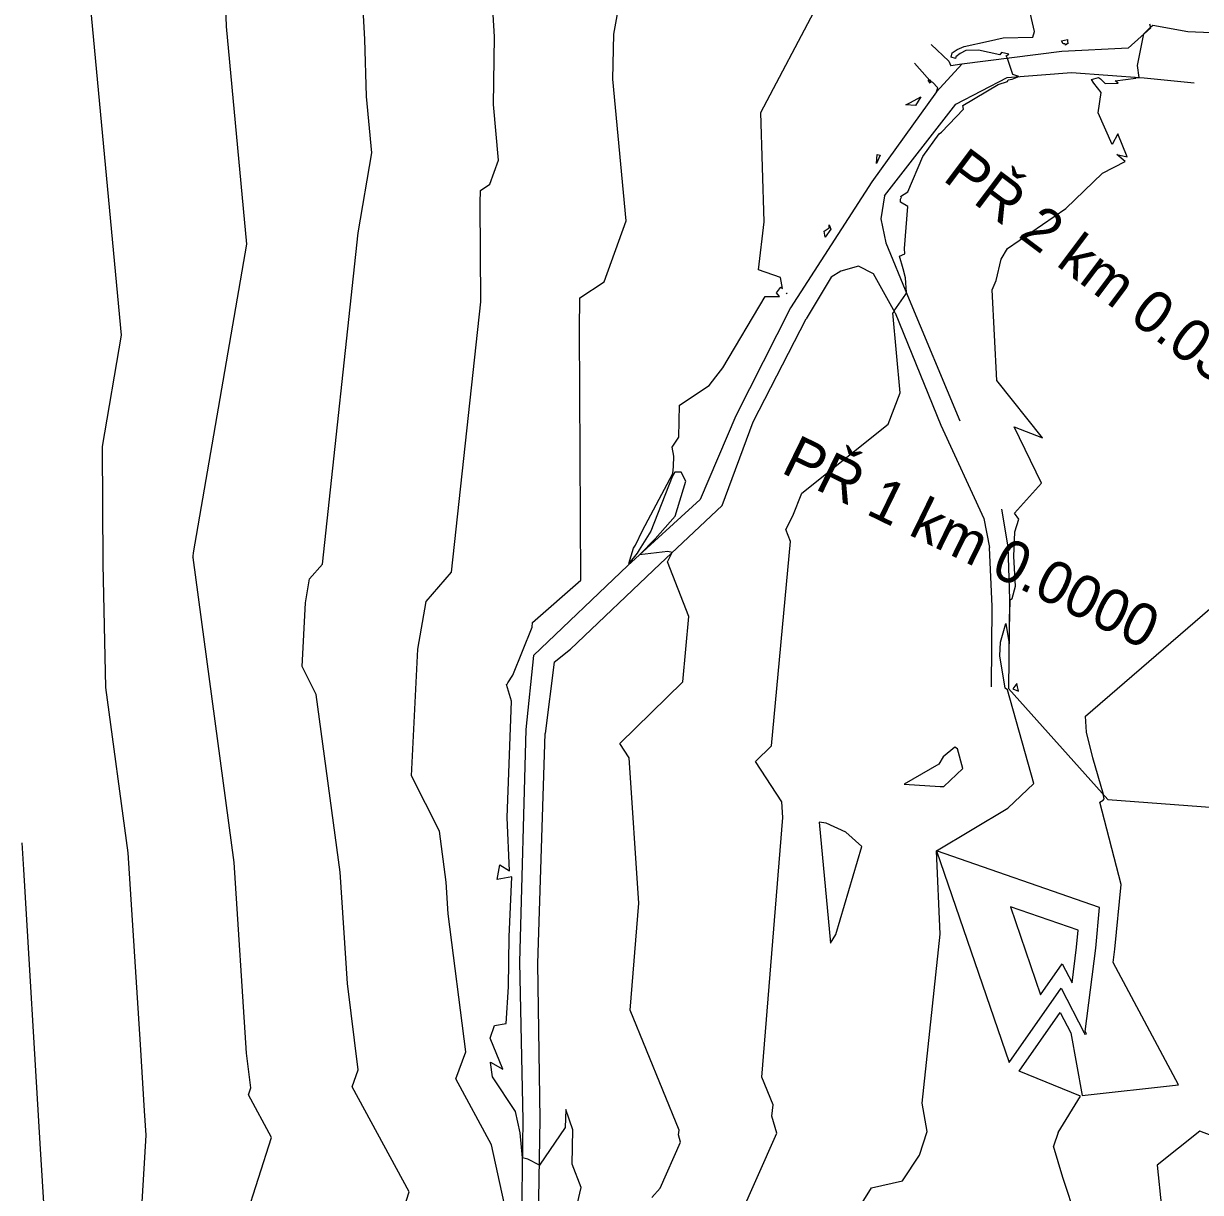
# Model space of a CAD drawing. Extents: x -549394 to -546608, y -1037055 to -1033629.
# Drawn here: x -547750.8 to -547499.1, y -1035351 to -1035100.8 of the extents above; entities that cross this region are included whole.
import ezdxf

# ---------------------------------------------------------------- set-up
doc = ezdxf.new("R2010")
doc.units = 0
for name, color, linetype in [('hlavni_vrst', 7, 'Continuous'), ('hrana_L', 7, 'Continuous'), ('norm_vrst', 7, 'Continuous'), ('x_popis_pricne_rezy_C141', 7, 'Continuous')]:
    doc.layers.add(name, color=color, linetype=linetype)

msp = doc.modelspace()

# ---------------------------------------------------------------- linework, layer by layer
at = {"layer": 'hlavni_vrst'}
for p, q in [((-547650.05, -1035103.66), (-547650.97, -1035088.23)), ((-547650.31, -1035118.13), (-547650.05, -1035103.66)), ((-547649.19, -1035130.07), (-547650.31, -1035118.13)), ((-547651.04, -1035135.21), (-547649.19, -1035130.07)), ((-547653.14, -1035139.23), (-547653.09, -1035136.56)), ((-547653.09, -1035136.56), (-547651.04, -1035135.21)), ((-547653.02, -1035160.36), (-547653.14, -1035139.23)), ((-547659.24, -1035218.22), (-547653.02, -1035160.36)), ((-547664.71, -1035224.5), (-547659.24, -1035218.22)), ((-547666.45, -1035234.7), (-547664.71, -1035224.5)), ((-547523.68, -1035249.07), (-547492.94, -1035222.45)), ((-547667.85, -1035261.83), (-547666.45, -1035234.7)), ((-547523.47, -1035252.45), (-547523.68, -1035249.07)), ((-547522.11, -1035257.98), (-547523.47, -1035252.45)), ((-547519.79, -1035265.79), (-547522.11, -1035257.98)), ((-547661.86, -1035273.67), (-547667.85, -1035261.83)), ((-547520.63, -1035267.42), (-547519.9, -1035266.99)), ((-547516.04, -1035285.05), (-547520.63, -1035267.42)), ((-547519.64, -1035266.74), (-547519.91, -1035265.75)), ((-547519.91, -1035265.75), (-547519.79, -1035265.79)), ((-547519.9, -1035266.99), (-547519.64, -1035266.74)), ((-547660.4, -1035284.55), (-547661.86, -1035273.67)), ((-547659.96, -1035291.34), (-547660.4, -1035284.55)), ((-547517.38, -1035298.89), (-547516.04, -1035285.05)), ((-547516.04, -1035285.05), (-547516.04, -1035285.05)), ((-547516.04, -1035285.05), (-547516.04, -1035285.05)), ((-547516.04, -1035285.05), (-547516.04, -1035285.05)), ((-547516.04, -1035285.05), (-547516.04, -1035285.05)), ((-547656.22, -1035320.85), (-547659.96, -1035291.34)), ((-547517.74, -1035301.73), (-547517.38, -1035298.89)), ((-547503.81, -1035327.94), (-547517.74, -1035301.73)), ((-547537.85, -1035324.99), (-547529.08, -1035312.43)), ((-547529.08, -1035312.43), (-547526.84, -1035316.77)), ((-547526.84, -1035316.77), (-547524.38, -1035330.2)), ((-547658.36, -1035326.65), (-547656.22, -1035320.85)), ((-547524.74, -1035330.33), (-547537.85, -1035324.99)), ((-547650.68, -1035340.75), (-547658.36, -1035326.65)), ((-547524.38, -1035330.2), (-547503.81, -1035327.94)), ((-547529.5, -1035338.11), (-547524.74, -1035330.33)), ((-547499.22, -1035337.83), (-547508.31, -1035345.11)), ((-547490.68, -1035341.09), (-547499.22, -1035337.83)), ((-547529.5, -1035338.11), (-547530.5, -1035341.08)), ((-547647.98, -1035353.14), (-547650.68, -1035340.75)), ((-547528.54, -1035347.72), (-547530.5, -1035341.08)), ((-547508.31, -1035345.11), (-547507.41, -1035354.07)), ((-547522.54, -1035365.68), (-547528.54, -1035347.72))]:
    msp.add_line(p, q, dxfattribs=at)
at = {"layer": 'hrana_L'}
for p, q in [((-547509.73, -1035101.72), (-547509.94, -1035101)), ((-547509.73, -1035101.72), (-547514.54, -1035106.1)), ((-547556.67, -1035105.35), (-547552.91, -1035108.87)), ((-547514.54, -1035106.1), (-547528.76, -1035106.82)), ((-547552.91, -1035108.87), (-547552.47, -1035109.91)), ((-547528.76, -1035106.82), (-547550.14, -1035109.56)), ((-547560.26, -1035109.29), (-547557.54, -1035112.36)), ((-547550.14, -1035109.56), (-547555.52, -1035115.44)), ((-547550.14, -1035109.56), (-547552.47, -1035109.91)), ((-547540.44, -1035112.37), (-547526.63, -1035111.28)), ((-547526.63, -1035111.28), (-547511.12, -1035112.47)), ((-547557.54, -1035112.36), (-547556.92, -1035113.1)), ((-547556.92, -1035113.1), (-547556.4, -1035113.41)), ((-547556.4, -1035113.41), (-547555.25, -1035114.57)), ((-547551.39, -1035118.06), (-547540.44, -1035112.37)), ((-547511.12, -1035112.47), (-547500.41, -1035113.54)), ((-547555.52, -1035115.44), (-547569.35, -1035134.71)), ((-547555.52, -1035115.44), (-547555.25, -1035114.57)), ((-547566.63, -1035137.73), (-547551.39, -1035118.06)), ((-547569.35, -1035134.71), (-547586.77, -1035161.66)), ((-547566.63, -1035137.73), (-547567.41, -1035142.61)), ((-547567.41, -1035142.61), (-547566.36, -1035147.78)), ((-547566.36, -1035147.78), (-547561.74, -1035159)), ((-547575.97, -1035153.82), (-547578.03, -1035155.14)), ((-547572.21, -1035152.78), (-547575.97, -1035153.82)), ((-547569.03, -1035154.36), (-547572.21, -1035152.78)), ((-547578.03, -1035155.14), (-547583.42, -1035164.02)), ((-547564.35, -1035162.73), (-547569.03, -1035154.36)), ((-547561.74, -1035159), (-547550.54, -1035185.88)), ((-547586.77, -1035161.66), (-547598.46, -1035184.75)), ((-547594.73, -1035186.07), (-547583.42, -1035164.02)), ((-547564.35, -1035162.73), (-547554.58, -1035186.78)), ((-547598.46, -1035184.75), (-547606.08, -1035202.67)), ((-547601.35, -1035203.97), (-547594.73, -1035186.07)), ((-547554.58, -1035186.78), (-547545.4, -1035206.76)), ((-547606.08, -1035202.67), (-547621.54, -1035216.83)), ((-547614.62, -1035216.42), (-547601.35, -1035203.97)), ((-547545.4, -1035206.76), (-547544.22, -1035212.97)), ((-547541.65, -1035204.75), (-547540.31, -1035212.84)), ((-547543.64, -1035225.54), (-547544.22, -1035212.97)), ((-547540.31, -1035212.84), (-547539.9, -1035223.97)), ((-547621.54, -1035216.83), (-547641.73, -1035236.08)), ((-547633.84, -1035234.67), (-547614.62, -1035216.42)), ((-547539.9, -1035223.97), (-547540.11, -1035243.13)), ((-547543.79, -1035242.77), (-547543.64, -1035225.54)), ((-547637.32, -1035237.51), (-547633.84, -1035234.67)), ((-547641.73, -1035236.08), (-547643.38, -1035251.89)), ((-547637.32, -1035237.51), (-547639.26, -1035252.74)), ((-547540.11, -1035243.13), (-547518.88, -1035266.9)), ((-547643.38, -1035251.89), (-547644.7, -1035301.66)), ((-547640.79, -1035301.94), (-547639.26, -1035252.74)), ((-547518.88, -1035266.9), (-547496.05, -1035268.59)), ((-547644.7, -1035301.66), (-547643.97, -1035335.51)), ((-547640.27, -1035335.27), (-547640.79, -1035301.94)), ((-547643.97, -1035335.51), (-547644.38, -1035361.94)), ((-547640.75, -1035362.22), (-547640.27, -1035335.27))]:
    msp.add_line(p, q, dxfattribs=at)
at = {"layer": 'norm_vrst'}
for p, q in [((-547624.56, -1035103.1), (-547617.56, -1035064.71)), ((-547707.41, -1035101.49), (-547708.32, -1035068.47)), ((-547677.77, -1035104.15), (-547679.55, -1035074.12)), ((-547729.82, -1035167.54), (-547737.39, -1035086.56)), ((-547593.1, -1035119.88), (-547581.07, -1035097.02)), ((-547534.57, -1035102.57), (-547535.61, -1035097.89)), ((-547509.75, -1035101.64), (-547509.24, -1035101.21)), ((-547509.24, -1035101.21), (-547501.78, -1035102.57)), ((-547703.06, -1035148.01), (-547707.41, -1035101.49)), ((-547624.74, -1035112.74), (-547624.56, -1035103.1)), ((-547544.42, -1035104.64), (-547541.25, -1035103.92)), ((-547541.25, -1035103.92), (-547534.92, -1035103.73)), ((-547534.92, -1035103.73), (-547534.57, -1035102.57)), ((-547512.55, -1035109.82), (-547511.17, -1035103.03)), ((-547511.17, -1035103.03), (-547509.75, -1035101.64)), ((-547501.78, -1035102.57), (-547493.31, -1035102.92)), ((-547677.43, -1035116.42), (-547677.77, -1035104.15)), ((-547552.18, -1035107.09), (-547551.08, -1035106.42)), ((-547551.08, -1035106.42), (-547549.61, -1035105.76)), ((-547549.61, -1035105.76), (-547544.42, -1035104.64)), ((-547528.79, -1035104.51), (-547527.52, -1035104.28)), ((-547528.43, -1035105.18), (-547528.79, -1035104.51)), ((-547528, -1035105.18), (-547528.43, -1035105.18)), ((-547527.97, -1035105.44), (-547528, -1035105.18)), ((-547527.34, -1035105.07), (-547527.97, -1035105.44)), ((-547527.52, -1035104.28), (-547527.55, -1035104.73)), ((-547527.55, -1035104.73), (-547527.34, -1035105.07)), ((-547552.39, -1035108.05), (-547552.18, -1035107.09)), ((-547551.47, -1035108.32), (-547552.39, -1035108.05)), ((-547551.4, -1035107.96), (-547551.47, -1035108.32)), ((-547550.47, -1035107.26), (-547551.4, -1035107.96)), ((-547549.23, -1035106.57), (-547550.47, -1035107.26)), ((-547546.54, -1035106.51), (-547549.23, -1035106.57)), ((-547541.97, -1035107.51), (-547546.54, -1035106.51)), ((-547541.62, -1035107.03), (-547541.97, -1035107.51)), ((-547540.08, -1035107.36), (-547541.62, -1035107.03)), ((-547540.65, -1035107.76), (-547540.08, -1035107.36)), ((-547540.35, -1035108.31), (-547540.65, -1035107.76)), ((-547539.18, -1035111.77), (-547540.35, -1035108.31)), ((-547512.17, -1035112.39), (-547512.55, -1035109.82)), ((-547621.88, -1035143.04), (-547624.74, -1035112.74)), ((-547557.29, -1035112.96), (-547557.19, -1035112.78)), ((-547556.91, -1035113.61), (-547557.29, -1035112.96)), ((-547557.19, -1035112.78), (-547556.86, -1035112.88)), ((-547556.76, -1035113.2), (-547556.91, -1035113.61)), ((-547556.86, -1035112.88), (-547556.76, -1035113.2)), ((-547549.9, -1035118.39), (-547542.36, -1035113.9)), ((-547542.36, -1035113.9), (-547540.37, -1035113.22)), ((-547540.37, -1035113.22), (-547540.19, -1035112.88)), ((-547540.19, -1035112.88), (-547539.36, -1035112.71)), ((-547539.36, -1035112.71), (-547537.9, -1035112.17)), ((-547537.9, -1035112.17), (-547539.18, -1035111.77)), ((-547522.36, -1035112.78), (-547520.92, -1035112.39)), ((-547521.86, -1035113.6), (-547522.36, -1035112.78)), ((-547520.33, -1035115.59), (-547521.86, -1035113.6)), ((-547520.92, -1035112.39), (-547520.45, -1035112.67)), ((-547520.45, -1035112.67), (-547519.48, -1035113.67)), ((-547519.48, -1035113.67), (-547516.67, -1035113.57)), ((-547517.3, -1035113.1), (-547512.88, -1035112.5)), ((-547516.67, -1035113.57), (-547517.3, -1035113.1)), ((-547513.13, -1035112.4), (-547512.17, -1035112.39)), ((-547512.88, -1035112.5), (-547513.13, -1035112.4)), ((-547676.31, -1035128.48), (-547677.43, -1035116.42)), ((-547520.94, -1035119.91), (-547520.33, -1035115.59)), ((-547562.08, -1035118.24), (-547561.09, -1035117.72)), ((-547560.06, -1035118.37), (-547562.08, -1035118.24)), ((-547561.09, -1035117.72), (-547558.85, -1035116.54)), ((-547558.85, -1035116.54), (-547560.06, -1035118.37)), ((-547549.77, -1035119.14), (-547549.9, -1035118.39)), ((-547592.42, -1035143.29), (-547593.1, -1035119.88)), ((-547554.44, -1035124.11), (-547549.77, -1035119.14)), ((-547517.94, -1035126.69), (-547520.94, -1035119.91)), ((-547558.45, -1035129.26), (-547554.97, -1035124.44)), ((-547554.97, -1035124.44), (-547554.44, -1035124.11)), ((-547516.76, -1035124.47), (-547517.94, -1035126.69)), ((-547514.77, -1035129.37), (-547516.76, -1035124.47)), ((-547679.25, -1035145.61), (-547676.31, -1035128.48)), ((-547568.37, -1035130.8), (-547568.19, -1035128.87)), ((-547567.58, -1035129.02), (-547568.37, -1035130.8)), ((-547568.19, -1035128.87), (-547567.58, -1035129.02)), ((-547515.15, -1035130.32), (-547516.97, -1035128.88)), ((-547516.97, -1035128.88), (-547514.77, -1035129.37)), ((-547561.65, -1035136.86), (-547558.45, -1035129.26)), ((-547520.05, -1035132.83), (-547515.15, -1035130.32)), ((-547527.89, -1035140.38), (-547520.05, -1035132.83)), ((-547563.23, -1035137.82), (-547561.65, -1035136.86)), ((-547563.02, -1035137.96), (-547563.23, -1035137.82)), ((-547563.23, -1035139.05), (-547563.22, -1035138.41)), ((-547561.64, -1035139.98), (-547563.23, -1035139.05)), ((-547563.22, -1035138.41), (-547563.02, -1035137.96)), ((-547562.37, -1035148.95), (-547561.64, -1035139.98)), ((-547540.33, -1035148.97), (-547527.89, -1035140.38)), ((-547626.58, -1035156.08), (-547621.88, -1035143.04)), ((-547593.6, -1035153.5), (-547592.42, -1035143.29)), ((-547578.47, -1035144.58), (-547578.46, -1035143.93)), ((-547578.46, -1035143.93), (-547578.12, -1035144.81)), ((-547686.87, -1035216.5), (-547679.25, -1035145.61)), ((-547579.54, -1035145.23), (-547578.47, -1035144.58)), ((-547579.31, -1035146.56), (-547579.54, -1035145.23)), ((-547578.12, -1035144.81), (-547579.31, -1035146.56)), ((-547714.43, -1035214.09), (-547703.06, -1035148.01)), ((-547562.32, -1035150.12), (-547562.37, -1035148.95)), ((-547541.7, -1035151.24), (-547540.33, -1035148.97)), ((-547563.44, -1035150.64), (-547562.32, -1035150.12)), ((-547562.68, -1035153.31), (-547563.44, -1035150.64)), ((-547542.76, -1035155.82), (-547541.7, -1035151.24)), ((-547588.91, -1035155.18), (-547593.6, -1035153.5)), ((-547562.19, -1035155.28), (-547562.68, -1035153.31)), ((-547631.79, -1035159.52), (-547626.58, -1035156.08)), ((-547588.5, -1035157.53), (-547588.91, -1035155.18)), ((-547561.92, -1035158.36), (-547562.19, -1035155.28)), ((-547543.6, -1035157.83), (-547542.76, -1035155.82)), ((-547601.22, -1035174.47), (-547592.16, -1035159.27)), ((-547592.16, -1035159.27), (-547589.1, -1035159.23)), ((-547589.75, -1035158.44), (-547588.88, -1035157.29)), ((-547589.1, -1035159.23), (-547589.75, -1035158.44)), ((-547588.88, -1035157.29), (-547588.86, -1035157.27)), ((-547588.86, -1035157.27), (-547588.5, -1035157.53)), ((-547587.69, -1035158.67), (-547587.56, -1035158.52)), ((-547587.52, -1035158.57), (-547587.69, -1035158.67)), ((-547587.56, -1035158.52), (-547587.5, -1035158.56)), ((-547587.5, -1035158.56), (-547587.52, -1035158.57)), ((-547564.6, -1035162.29), (-547562.12, -1035158.76)), ((-547562.12, -1035158.76), (-547561.93, -1035158.53)), ((-547561.93, -1035158.53), (-547561.92, -1035158.36)), ((-547542.66, -1035177.19), (-547543.6, -1035157.83)), ((-547631.92, -1035166.29), (-547631.79, -1035159.52)), ((-547564.89, -1035162.77), (-547564.66, -1035162.56)), ((-547563.32, -1035179.88), (-547564.89, -1035162.77)), ((-547564.66, -1035162.56), (-547564.6, -1035162.29)), ((-547631.61, -1035219.94), (-547631.92, -1035166.29)), ((-547733.91, -1035191.31), (-547729.82, -1035167.54)), ((-547604.18, -1035178.32), (-547602.75, -1035176.44)), ((-547602.75, -1035176.44), (-547601.22, -1035174.47)), ((-547610.48, -1035182.48), (-547604.18, -1035178.32)), ((-547532.84, -1035189.49), (-547542.66, -1035177.19)), ((-547565.84, -1035186.58), (-547563.32, -1035179.88)), ((-547610.62, -1035189.35), (-547610.48, -1035182.48)), ((-547584.35, -1035201.32), (-547565.84, -1035186.58)), ((-547612.07, -1035191.49), (-547610.62, -1035189.35)), ((-547533.05, -1035199.15), (-547538.95, -1035187.12)), ((-547538.95, -1035187.12), (-547532.84, -1035189.49)), ((-547733.75, -1035216.48), (-547733.91, -1035191.31)), ((-547611.68, -1035193.42), (-547612.07, -1035191.49)), ((-547611.81, -1035195.6), (-547611.68, -1035193.42)), ((-547611.48, -1035196.86), (-547612.06, -1035197.8)), ((-547611.89, -1035197.08), (-547611.81, -1035195.6)), ((-547610.15, -1035196.85), (-547611.48, -1035196.86)), ((-547609.14, -1035198.73), (-547610.15, -1035196.85)), ((-547618.41, -1035209.34), (-547611.89, -1035197.08)), ((-547612.06, -1035197.8), (-547616.65, -1035209.42)), ((-547611.4, -1035206.28), (-547609.14, -1035198.73)), ((-547538.82, -1035205.63), (-547533.05, -1035199.15)), ((-547586.27, -1035206.2), (-547584.35, -1035201.32)), ((-547615.71, -1035211.11), (-547611.4, -1035206.28)), ((-547587.78, -1035209.07), (-547586.27, -1035206.2)), ((-547537.95, -1035206.9), (-547538.82, -1035205.63)), ((-547538.8, -1035209.61), (-547537.95, -1035206.9)), ((-547619.9, -1035212.42), (-547618.41, -1035209.34)), ((-547616.65, -1035209.42), (-547619.1, -1035213.44)), ((-547586.75, -1035211.7), (-547587.78, -1035209.07)), ((-547538.96, -1035214.88), (-547538.8, -1035209.61)), ((-547619.05, -1035214.55), (-547615.71, -1035211.11)), ((-547590.83, -1035255.39), (-547586.75, -1035211.7)), ((-547714.5, -1035214.79), (-547714.43, -1035214.09)), ((-547621.33, -1035216.4), (-547620.37, -1035213.07)), ((-547619.54, -1035214.18), (-547621.33, -1035216.4)), ((-547620.37, -1035213.07), (-547619.9, -1035212.42)), ((-547619.1, -1035213.44), (-547619.54, -1035214.18)), ((-547613.02, -1035213.84), (-547619.05, -1035214.55)), ((-547613.1, -1035216), (-547612.05, -1035214.01)), ((-547612.05, -1035214.01), (-547613.02, -1035213.84)), ((-547733.18, -1035242.89), (-547733.75, -1035216.48)), ((-547714.55, -1035215), (-547714.54, -1035214.87)), ((-547714.52, -1035215.06), (-547714.55, -1035215)), ((-547714.54, -1035214.87), (-547714.53, -1035214.82)), ((-547714.53, -1035214.82), (-547714.5, -1035214.79)), ((-547705.75, -1035280.36), (-547714.52, -1035215.06)), ((-547689.62, -1035219.66), (-547686.87, -1035216.5)), ((-547608.51, -1035227.72), (-547613.1, -1035216)), ((-547538.67, -1035221.2), (-547538.96, -1035214.88)), ((-547690.49, -1035224.79), (-547689.62, -1035219.66)), ((-547641.91, -1035229.02), (-547631.61, -1035219.94)), ((-547631.61, -1035219.94), (-547631.61, -1035219.94)), ((-547631.61, -1035219.94), (-547631.61, -1035219.94)), ((-547631.61, -1035219.94), (-547631.61, -1035219.94)), ((-547631.61, -1035219.94), (-547631.61, -1035219.94)), ((-547631.61, -1035219.94), (-547631.61, -1035219.94)), ((-547631.61, -1035219.94), (-547631.61, -1035219.94)), ((-547539.33, -1035223.84), (-547538.67, -1035221.2)), ((-547540.01, -1035233.55), (-547539.76, -1035224.13)), ((-547539.76, -1035224.13), (-547539.33, -1035223.84)), ((-547691.2, -1035238.41), (-547690.49, -1035224.79)), ((-547641.99, -1035229.96), (-547641.91, -1035229.02)), ((-547609.82, -1035241.69), (-547608.51, -1035227.72)), ((-547541.85, -1035233.2), (-547540.73, -1035229.23)), ((-547540.73, -1035229.23), (-547540.01, -1035233.55)), ((-547646.14, -1035240.29), (-547641.99, -1035229.96)), ((-547542, -1035236.14), (-547541.85, -1035233.2)), ((-547540.85, -1035243.06), (-547542, -1035236.14)), ((-547688.19, -1035244.37), (-547691.2, -1035238.41)), ((-547647.48, -1035242.29), (-547647.34, -1035242.17)), ((-547646.4, -1035245.8), (-547647.48, -1035242.29)), ((-547647.34, -1035242.17), (-547647.18, -1035241.93)), ((-547647.18, -1035241.93), (-547646.14, -1035240.29)), ((-547623.29, -1035254.87), (-547609.82, -1035241.69)), ((-547538.33, -1035242.06), (-547539.23, -1035243.18)), ((-547538.19, -1035242.73), (-547538.33, -1035242.06)), ((-547728.43, -1035278.26), (-547733.18, -1035242.89)), ((-547683.08, -1035282.45), (-547688.19, -1035244.37)), ((-547540.32, -1035243.38), (-547540.85, -1035243.06)), ((-547534.75, -1035263.47), (-547540.32, -1035243.38)), ((-547539.23, -1035243.18), (-547538, -1035243.67)), ((-547538.09, -1035243.35), (-547538.19, -1035242.73)), ((-547538, -1035243.67), (-547538.09, -1035243.35)), ((-547647.37, -1035270.69), (-547646.4, -1035245.8)), ((-547621.29, -1035257.93), (-547623.29, -1035254.87)), ((-547594.25, -1035258.73), (-547590.83, -1035255.39)), ((-547551.59, -1035255.7), (-547554.08, -1035257.72)), ((-547551.02, -1035256.06), (-547551.59, -1035255.7)), ((-547549.87, -1035260.21), (-547551.02, -1035256.06)), ((-547619.22, -1035289.08), (-547621.29, -1035257.93)), ((-547588.62, -1035267.38), (-547594.25, -1035258.73)), ((-547555.06, -1035259.28), (-547562.42, -1035263.57)), ((-547554.08, -1035257.72), (-547555.06, -1035259.28)), ((-547553.94, -1035264.07), (-547549.87, -1035260.21)), ((-547562.42, -1035263.57), (-547554.76, -1035264.08)), ((-547554.76, -1035264.08), (-547553.94, -1035264.07)), ((-547540.26, -1035268.7), (-547534.75, -1035263.47)), ((-547588.4, -1035270.71), (-547588.62, -1035267.38)), ((-547555.53, -1035277.84), (-547540.26, -1035268.7)), ((-547646.84, -1035282.11), (-547647.37, -1035270.69)), ((-547592.87, -1035326.29), (-547588.4, -1035270.71)), ((-547579.11, -1035271.92), (-547580.64, -1035271.7)), ((-547580.64, -1035271.7), (-547578.17, -1035297.63)), ((-547574.92, -1035273.89), (-547579.11, -1035271.92)), ((-547571.48, -1035276.95), (-547574.92, -1035273.89)), ((-547750.74, -1035281.82), (-547751.1, -1035276.17)), ((-547577.08, -1035295.74), (-547571.48, -1035276.95)), ((-547725.77, -1035319.26), (-547728.43, -1035278.26)), ((-547555.53, -1035277.84), (-547540, -1035323.18)), ((-547520.64, -1035289.95), (-547555.53, -1035277.84)), ((-547555.53, -1035277.84), (-547555.53, -1035277.84)), ((-547555.53, -1035277.84), (-547555.53, -1035277.84)), ((-547554.72, -1035295.66), (-547555.53, -1035277.84)), ((-547747.23, -1035340.5), (-547750.74, -1035281.82)), ((-547703.11, -1035321.12), (-547705.75, -1035280.36)), ((-547681.53, -1035306.23), (-547683.08, -1035282.45)), ((-547649.47, -1035284), (-547648.93, -1035280.83)), ((-547648.93, -1035280.83), (-547646.84, -1035282.11)), ((-547646.39, -1035283.4), (-547649.47, -1035284)), ((-547646.91, -1035296.24), (-547646.39, -1035283.4)), ((-547621.06, -1035311.97), (-547619.22, -1035289.08)), ((-547539.72, -1035289.82), (-547533.28, -1035308.65)), ((-547525.24, -1035294.85), (-547539.72, -1035289.82)), ((-547521.48, -1035298.68), (-547520.64, -1035289.95)), ((-547525.59, -1035298.48), (-547525.24, -1035294.85)), ((-547647.08, -1035306.99), (-547646.91, -1035296.24)), ((-547578.17, -1035297.63), (-547577.08, -1035295.74)), ((-547558.62, -1035331.87), (-547554.72, -1035295.66)), ((-547526.55, -1035306.09), (-547525.59, -1035298.48)), ((-547523.75, -1035316.49), (-547521.48, -1035298.68)), ((-547533.28, -1035308.65), (-547528.65, -1035302.02)), ((-547528.65, -1035302.02), (-547526.55, -1035306.09)), ((-547679.19, -1035324.73), (-547681.53, -1035306.23)), ((-547647.58, -1035314.77), (-547647.08, -1035306.99)), ((-547540, -1035323.18), (-547528.87, -1035307.23)), ((-547528.87, -1035307.23), (-547523.93, -1035316.79)), ((-547610.58, -1035337.62), (-547621.06, -1035311.97)), ((-547650.97, -1035317.97), (-547650.06, -1035315.22)), ((-547650.06, -1035315.22), (-547647.58, -1035314.77)), ((-547523.93, -1035316.79), (-547523.88, -1035317.05)), ((-547523.88, -1035317.05), (-547523.48, -1035317.01)), ((-547523.48, -1035317.01), (-547523.75, -1035316.49)), ((-547724.92, -1035333.48), (-547725.77, -1035319.26)), ((-547648.26, -1035324.59), (-547650.97, -1035317.97)), ((-547702.16, -1035328.6), (-547703.11, -1035321.12)), ((-547680.53, -1035328.36), (-547679.19, -1035324.73)), ((-547650.91, -1035323.15), (-547650.93, -1035323.1)), ((-547650.93, -1035323.1), (-547648.26, -1035324.59)), ((-547650.51, -1035326.18), (-547650.91, -1035323.15)), ((-547645.58, -1035333.62), (-547650.51, -1035326.18)), ((-547590.45, -1035332.21), (-547592.87, -1035326.29)), ((-547702.7, -1035330.07), (-547702.16, -1035328.6)), ((-547697.76, -1035339.16), (-547702.7, -1035330.07)), ((-547668.31, -1035350.8), (-547680.53, -1035328.36)), ((-547590.76, -1035334.61), (-547590.45, -1035332.21)), ((-547557.51, -1035337.94), (-547558.62, -1035331.87)), ((-547724.59, -1035338.68), (-547724.92, -1035333.48)), ((-547644.58, -1035338.2), (-547645.58, -1035333.62)), ((-547634.82, -1035333.18), (-547634.95, -1035337.04)), ((-547633.32, -1035337.57), (-547634.82, -1035333.18)), ((-547589.66, -1035338.3), (-547590.76, -1035334.61)), ((-547634.95, -1035337.04), (-547640.45, -1035345.11)), ((-547633.43, -1035344.88), (-547633.32, -1035337.57)), ((-547610.71, -1035338.63), (-547610.58, -1035337.62)), ((-547559.2, -1035342.97), (-547557.51, -1035337.94)), ((-547745.88, -1035361.93), (-547747.23, -1035340.5)), ((-547728.43, -1035406.99), (-547724.59, -1035338.68)), ((-547705.79, -1035364.36), (-547697.76, -1035339.16)), ((-547644.1, -1035343.57), (-547644.58, -1035338.2)), ((-547614.65, -1035350.07), (-547610.25, -1035340.19)), ((-547610.25, -1035340.19), (-547610.71, -1035338.63)), ((-547600.1, -1035361.72), (-547589.66, -1035338.3)), ((-547562.77, -1035348.49), (-547559.2, -1035342.97)), ((-547642.97, -1035343.8), (-547644.1, -1035343.57)), ((-547640.45, -1035345.11), (-547642.97, -1035343.8)), ((-547631.51, -1035349.89), (-547633.43, -1035344.88)), ((-547634.71, -1035363.08), (-547631.51, -1035349.89)), ((-547616.41, -1035352.04), (-547614.65, -1035350.07)), ((-547575.42, -1035359.56), (-547569.4, -1035349.98)), ((-547569.4, -1035349.98), (-547562.77, -1035348.49)), ((-547680.29, -1035388.4), (-547668.31, -1035350.8))]:
    msp.add_line(p, q, dxfattribs=at)

# ---------------------------------------------------------------- texts
at = {"layer": 'x_popis_pricne_rezy_C141'}
for s, rotation, p in [('PŘ 2 km 0.0300', 323.0982, (-547554.45, -1035134.22)), ('PŘ 1 km 0.0000', 334.0053, (-547589.05, -1035196.79))]:
    msp.add_text(s, height=9.0627, rotation=rotation, dxfattribs=at).set_placement(p)

doc.saveas('drawing.dxf')
